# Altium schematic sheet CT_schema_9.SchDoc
size 274 x 160 mm
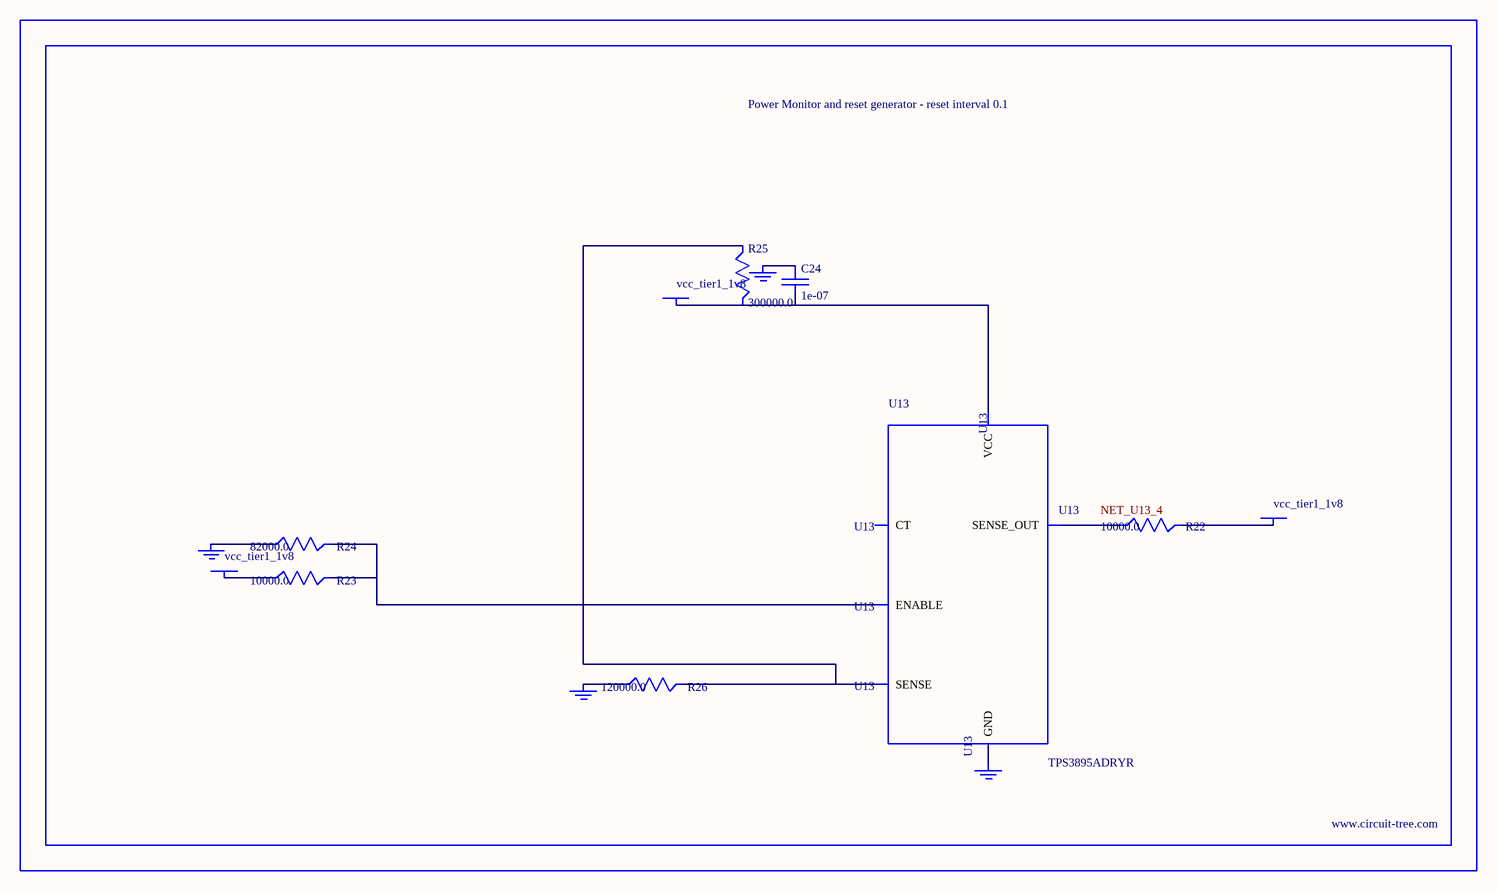
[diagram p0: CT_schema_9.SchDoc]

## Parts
BORDER8  (no value)
C24  1e-07  [C0402]
GND_INSTANCE_8_0  (no value)
GND_INSTANCE_8_1  (no value)
GND_INSTANCE_8_2  (no value)
GND_INSTANCE_8_3  (no value)
POWER_INSTANCE_8_0  vcc_tier1_1v8
POWER_INSTANCE_8_1  vcc_tier1_1v8
POWER_INSTANCE_8_2  vcc_tier1_1v8
R22  10000.0  [R0603]
R23  10000.0  [R0603]
R24  82000.0  [R0603]
R25  300000.0  [R0603]
R26  120000.0  [R0603]
U13  TPS3895ADRYR  [SON-6]

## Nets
NetC24_1: C24.1 GND_INSTANCE_8_2.0(GND)
NetC24_2: C24.2 POWER_INSTANCE_8_2.0(PWR) R25.2 U13.6(VCC)
NetGND_INSTANCE_8_0_0: GND_INSTANCE_8_0.0(GND) R24.1
NetGND_INSTANCE_8_1_0: GND_INSTANCE_8_1.0(GND) R26.1
NetGND_INSTANCE_8_3_0: GND_INSTANCE_8_3.0(GND) U13.2(GND)
NetPOWER_INSTANCE_8_0_0: POWER_INSTANCE_8_0.0(PWR) R23.1
NetPOWER_INSTANCE_8_1_0: POWER_INSTANCE_8_1.0(PWR) R22.2
NetR22_1: R22.1 U13.4(SENSE_OUT)
NetR23_2: R23.2 R24.2 U13.1(ENABLE)
NetR25_1: R25.1 R26.2 U13.3(SENSE)

Not connected (* = marked no-connect by the designer): U13 5(CT)

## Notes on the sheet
- Labels drawn without touching a wire or pin: NET_U13_4

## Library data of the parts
BORDER8 = BORDER_PAGE8
C24 = C0402C104K3RACTU
GND_INSTANCE_8_0-GND_INSTANCE_8_3 = GND
POWER_INSTANCE_8_0-POWER_INSTANCE_8_2 = PWR
R22 R23 = RC0603JR-0710KL
R24 = RC0603JR-0782KL
R25 = RC0603JR-07300KL
R26 = RC0603JR-07120KL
